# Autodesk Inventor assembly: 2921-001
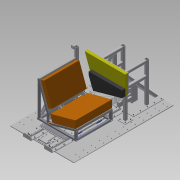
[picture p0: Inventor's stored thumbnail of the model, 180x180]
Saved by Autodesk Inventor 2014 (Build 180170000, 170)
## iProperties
Company: NHTSA/VRTC
Created: 2012-12
Part Number: 2921-001
Document SubType Name: Assembly
Designer: Mike Vanvoorhis
Project: CHILD SIDE IMPACT SLED
Description: CHILD SIDE IMPACT SLED ASS'Y.
Author: Dave Walker
Title: Child Side Impact Sled Ass'y.
Subject: Child Side Impact Sled
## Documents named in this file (22)
- B:\VRTC_DWG\BIO\Non-P572\Child Side-Frontal Impact Sled\Side Impact Sled\Sled_Buck_Assembly.iam
- B:\VRTC_DWG\BIO\Non-P572\Child Side-Frontal Impact Sled\Side Impact Sled\VRTC_Base_Plate.ipt
- B:\VRTC_DWG\BIO\Non-P572\Child Side-Frontal Impact Sled\Side Impact Sled\Impactor_Frame_Assembly_5.iam
- B:\VRTC_DWG\Inventor Support Files\Content Center\en-US\ANSI B18.3.1M(6)\ANSI B18.3.1M - M12x1.75 x 20(1).ipt
- B:\VRTC_DWG\BIO\Non-P572\Child Side-Frontal Impact Sled\Side Impact Sled\Rail_Assembly.iam
- B:\VRTC_DWG\Inventor Support Files\Content Center\en-US\ANSI B18.3(05)\ANSI B18.3 - 1_2-13 UNC - 1(31).ipt
- B:\VRTC_DWG\BIO\Non-P572\Child Side-Frontal Impact Sled\Side Impact Sled\Bench_Assembly.iam
- B:\VRTC_DWG\Inventor Support Files\Content Center\en-US\ANSI B18.3.1M(6)\ANSI B18.3.1M - M8x1.25 x 30(1).ipt
- B:\VRTC_DWG\BIO\Non-P572\Child Side-Frontal Impact Sled\Side Impact Sled\Anti_Rebound_Fixture_Assembly-01.iam
- B:\VRTC_DWG\BIO\Non-P572\Child Side Impact Sled-Nov 2012\Workspaces\Workspace\Inventor Models\Anti_Rebound_Fixture_Assembly.iam
- B:\VRTC_DWG\Inventor Support Files\Content Center\en-US\ANSI ASME B18.2.1(2)\ANSI_ASME B18.2.1 - 5_8-11 UNC - 1.5(2).ipt
- B:\VRTC_DWG\Inventor Support Files\Content Center\en-US\ANSI B18.21.1\ANSI B18.21.1 - 0.625.ipt
- B:\VRTC_DWG\Inventor Support Files\Content Center\en-US\ANSI B18.2.2(09)\ANSI B18.2.2 - 5_8 - 11(2).ipt
- B:\VRTC_DWG\BIO\Non-P572\Child Side-Frontal Impact Sled\Side Impact Sled\RightSide_Bumper.iam
- B:\VRTC_DWG\BIO\Non-P572\Child Side-Frontal Impact Sled\Side Impact Sled\LeftSide_Bumper.iam
- B:\VRTC_DWG\BIO\Non-P572\Child Side-Frontal Impact Sled\Side Impact Sled\Impactor Door Foam Assembly.iam
- B:\VRTC_DWG\BIO\Non-P572\Child Side-Frontal Impact Sled\Side Impact Sled\Honeycomb.ipt
- B:\VRTC_DWG\BIO\Non-P572\Child Side-Frontal Impact Sled\Side Impact Sled\Light Trap Mount Assembly.iam
- B:\VRTC_DWG\BIO\Non-P572\Child Side-Frontal Impact Sled\Side Impact Sled\Light Trap Sensor.ipt
- B:\VRTC_DWG\Inventor Support Files\Content Center\en-US\ANSI B18.3(05)\ANSI B18.3 - 3_8-24 UNF - 0.5(31).ipt
- B:\VRTC_DWG\Inventor Support Files\Content Center\en-US\ANSI ASME B18.2.1(2)\ANSI_ASME B18.2.1 - 5_8-11 UNC - 1.75(2).ipt
- B:\VRTC_DWG\Inventor Support Files\Content Center\en-US\ANSI B18.3(05)\ANSI B18.3 - 1_2-13 UNC - 1.25(31).ipt
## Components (117 placed, 20 different names)
1. VRTC_Base_Plate:1 — Insert:1, Angle:1, Insert:24, Insert:25, Insert:26, Insert:27, Insert:83, Insert:84, Insert:93, Insert:94, Insert:95, Insert:96, Insert:97, Insert:98, Insert:99, Insert:100, Flush:6, Insert:119, Insert:120, Insert:125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
2. Impactor_Frame_Assembly_5:1 [sub-assembly] — Insert:1, Angle:1, Insert:3, Insert:4, Insert:5, Insert:6, Insert:7, Insert:8, Insert:9, Insert:10, Insert:11, Insert:12, Insert:13, Insert:14, Insert:15, Insert:16, Insert:17, Insert:18, Insert:19, Insert:20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
3. Rail_Assembly:1 [sub-assembly] — Insert:24, Insert:25, Flush:1, Flush:2, Insert:49, Insert:50, Insert:51, Insert:52, Insert:53, Insert:54, Insert:55, Insert:56, Insert:57, Insert:58, Insert:59, Insert:60, Insert:61, Insert:62, Insert:63, Insert:64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
4. Rail_Assembly:2 [sub-assembly] — Insert:26, Insert:27, Flush:1, Flush:2, Insert:30, Insert:31, Insert:32, Insert:33, Insert:34, Insert:35, Insert:36, Insert:37, Insert:38, Insert:39, Insert:40, Insert:41, Insert:42, Insert:43, Insert:44, Insert:65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
5. Bench_Assembly:1 [sub-assembly] — Insert:64, Insert:65, Insert:66, Flush:6
6. Anti_Rebound_Fixture_Assembly-01:1 [sub-assembly] — Insert:83, Insert:84, Insert:85, Insert:86, Insert:87, Insert:88, Insert:89, Insert:90, Insert:91, Insert:92
7. RightSide_Bumper:1 [sub-assembly] — Insert:109, Insert:110
8. LeftSide_Bumper:1 [sub-assembly] — Insert:111, Insert:112
9. Impactor Door Foam Assembly:1 [sub-assembly] — Mate:1, Flush:3, Flush:4
10. Honeycomb:1 — Mate:2, Mate:3, Mate:4, Flush:5
11. Light Trap Mount Assembly:1 [sub-assembly] — Insert:119, Insert:120, Insert:121, Angle:2, Insert:122, Insert:123, Insert:124
12. Light Trap Sensor:1 — Insert:121, Angle:2
13. Hexagon Socket Head Cap Screw - Inch 3/8-24 UNF - 0.5:1 — Insert:122
14. Hex Bolt - Inch 5/8-11 UNC - 1.75:1 — Insert:124
15. Hex Bolt - Inch 5/8-11 UNC - 1.75:2 — Insert:123
16. Helical Spring Lock Washers 0.625:9 — Insert:126, Insert:127
17. Helical Spring Lock Washers 0.625:10 — Insert:125, Insert:128
18. Hex Nut - Inch 5/8 - 11:9 — Insert:127
19. Hex Nut - Inch 5/8 - 11:10 — Insert:128
20. Forged Socket Head Cap Screw - Metric M12x1.75 x 20:1
21. Forged Socket Head Cap Screw - Metric M12x1.75 x 20:2 — Insert:3
22. Forged Socket Head Cap Screw - Metric M12x1.75 x 20:3 — Insert:4
23. Forged Socket Head Cap Screw - Metric M12x1.75 x 20:4 — Insert:5
24. Forged Socket Head Cap Screw - Metric M12x1.75 x 20:5 — Insert:6
25. Forged Socket Head Cap Screw - Metric M12x1.75 x 20:6 — Insert:7
26. Forged Socket Head Cap Screw - Metric M12x1.75 x 20:7 — Insert:8
27. Forged Socket Head Cap Screw - Metric M12x1.75 x 20:8 — Insert:12
28. Forged Socket Head Cap Screw - Metric M12x1.75 x 20:9 — Insert:11
29. Forged Socket Head Cap Screw - Metric M12x1.75 x 20:10 — Insert:10
30. Forged Socket Head Cap Screw - Metric M12x1.75 x 20:11 — Insert:9
31. Forged Socket Head Cap Screw - Metric M12x1.75 x 20:12 — Insert:13
32. Forged Socket Head Cap Screw - Metric M12x1.75 x 20:13 — Insert:14
33. Forged Socket Head Cap Screw - Metric M12x1.75 x 20:14 — Insert:15
34. Forged Socket Head Cap Screw - Metric M12x1.75 x 20:15 — Insert:19
35. Forged Socket Head Cap Screw - Metric M12x1.75 x 20:16 — Insert:18
36. Forged Socket Head Cap Screw - Metric M12x1.75 x 20:17 — Insert:17
37. Forged Socket Head Cap Screw - Metric M12x1.75 x 20:18 — Insert:16
38. Forged Socket Head Cap Screw - Metric M12x1.75 x 20:19 — Insert:20
39. Forged Socket Head Cap Screw - Metric M12x1.75 x 20:20 — Insert:21
40. Forged Socket Head Cap Screw - Metric M12x1.75 x 20:21 — Insert:22
41. Forged Socket Head Cap Screw - Metric M12x1.75 x 20:22 — Insert:23
42. Hexagon Socket Head Cap Screw - Inch 1/2 - 13 UNC - 1:3 — Insert:30
43. Hexagon Socket Head Cap Screw - Inch 1/2 - 13 UNC - 1:4 — Insert:31
44. Hexagon Socket Head Cap Screw - Inch 1/2 - 13 UNC - 1:5 — Insert:32
45. Hexagon Socket Head Cap Screw - Inch 1/2 - 13 UNC - 1:6 — Insert:33
46. Hexagon Socket Head Cap Screw - Inch 1/2 - 13 UNC - 1:7 — Insert:34
47. Hexagon Socket Head Cap Screw - Inch 1/2 - 13 UNC - 1:8 — Insert:35
48. Hexagon Socket Head Cap Screw - Inch 1/2 - 13 UNC - 1:9 — Insert:36
49. Hexagon Socket Head Cap Screw - Inch 1/2 - 13 UNC - 1:10 — Insert:37
50. Hexagon Socket Head Cap Screw - Inch 1/2 - 13 UNC - 1:11 — Insert:38
51. Hexagon Socket Head Cap Screw - Inch 1/2 - 13 UNC - 1:12 — Insert:39
52. Hexagon Socket Head Cap Screw - Inch 1/2 - 13 UNC - 1:13 — Insert:40
53. Hexagon Socket Head Cap Screw - Inch 1/2 - 13 UNC - 1:14 — Insert:41
54. Hexagon Socket Head Cap Screw - Inch 1/2 - 13 UNC - 1:15 — Insert:42
55. Hexagon Socket Head Cap Screw - Inch 1/2 - 13 UNC - 1:16 — Insert:44
56. Hexagon Socket Head Cap Screw - Inch 1/2 - 13 UNC - 1:19 — Insert:49
57. Hexagon Socket Head Cap Screw - Inch 1/2 - 13 UNC - 1:20 — Insert:51
58. Hexagon Socket Head Cap Screw - Inch 1/2 - 13 UNC - 1:21 — Insert:52
59. Hexagon Socket Head Cap Screw - Inch 1/2 - 13 UNC - 1:22 — Insert:54
60. Hexagon Socket Head Cap Screw - Inch 1/2 - 13 UNC - 1:23 — Insert:57
61. Hexagon Socket Head Cap Screw - Inch 1/2 - 13 UNC - 1:24 — Insert:58
62. Hexagon Socket Head Cap Screw - Inch 1/2 - 13 UNC - 1:25 — Insert:60
63. Hexagon Socket Head Cap Screw - Inch 1/2 - 13 UNC - 1:26 — Insert:63
64. Hexagon Socket Head Cap Screw - Inch 1/2 - 13 UNC - 1:27 — Insert:62
65. Hexagon Socket Head Cap Screw - Inch 1/2 - 13 UNC - 1:28 — Insert:61
66. Hexagon Socket Head Cap Screw - Inch 1/2 - 13 UNC - 1:29 — Insert:59
67. Hexagon Socket Head Cap Screw - Inch 1/2 - 13 UNC - 1:30 — Insert:56
68. Hexagon Socket Head Cap Screw - Inch 1/2 - 13 UNC - 1:31 — Insert:55
69. Hexagon Socket Head Cap Screw - Inch 1/2 - 13 UNC - 1:32 — Insert:53
70. Hexagon Socket Head Cap Screw - Inch 1/2 - 13 UNC - 1:33 — Insert:50
71. Hexagon Socket Head Cap Screw - Inch 1/2 - 13 UNC - 1:35 — Insert:43
72. Forged Socket Head Cap Screw - Metric M8x1.25 x 30:1 — Insert:67
73. Forged Socket Head Cap Screw - Metric M8x1.25 x 30:2 — Insert:68
74. Forged Socket Head Cap Screw - Metric M8x1.25 x 30:3 — Insert:69
75. Forged Socket Head Cap Screw - Metric M8x1.25 x 30:4 — Insert:70
76. Forged Socket Head Cap Screw - Metric M8x1.25 x 30:5 — Insert:72
77. Forged Socket Head Cap Screw - Metric M8x1.25 x 30:6 — Insert:71
78. Forged Socket Head Cap Screw - Metric M8x1.25 x 30:7 — Insert:73
79. Forged Socket Head Cap Screw - Metric M8x1.25 x 30:8 — Insert:74
80. Forged Socket Head Cap Screw - Metric M8x1.25 x 30:9 — Insert:75
81. Forged Socket Head Cap Screw - Metric M8x1.25 x 30:10 — Insert:76
82. Forged Socket Head Cap Screw - Metric M8x1.25 x 30:11 — Insert:78
83. Forged Socket Head Cap Screw - Metric M8x1.25 x 30:12 — Insert:77
84. Forged Socket Head Cap Screw - Metric M8x1.25 x 30:13 — Insert:79
85. Forged Socket Head Cap Screw - Metric M8x1.25 x 30:14 — Insert:80
86. Forged Socket Head Cap Screw - Metric M8x1.25 x 30:15 — Insert:81
87. Forged Socket Head Cap Screw - Metric M8x1.25 x 30:16 — Insert:82
88. Hex Bolt - Inch 5/8-11 UNC - 1.5:1 — Insert:85
89. Hex Bolt - Inch 5/8-11 UNC - 1.5:2 — Insert:86
90. Hex Bolt - Inch 5/8-11 UNC - 1.5:3 — Insert:87
91. Hex Bolt - Inch 5/8-11 UNC - 1.5:4 — Insert:88
92. Hex Bolt - Inch 5/8-11 UNC - 1.5:5 — Insert:89
93. Hex Bolt - Inch 5/8-11 UNC - 1.5:6 — Insert:90
94. Hex Bolt - Inch 5/8-11 UNC - 1.5:7 — Insert:91
95. Hex Bolt - Inch 5/8-11 UNC - 1.5:8 — Insert:92
96. Helical Spring Lock Washers 0.625:1 — Insert:97, Insert:105
97. Helical Spring Lock Washers 0.625:2 — Insert:99, Insert:107
98. Helical Spring Lock Washers 0.625:3 — Insert:98, Insert:106
99. Helical Spring Lock Washers 0.625:4 — Insert:100, Insert:108
100. Helical Spring Lock Washers 0.625:5 — Insert:96, Insert:104
101. Helical Spring Lock Washers 0.625:6 — Insert:93, Insert:101
102. Helical Spring Lock Washers 0.625:7 — Insert:95, Insert:103
103. Helical Spring Lock Washers 0.625:8 — Insert:94, Insert:102
104. Hex Nut - Inch 5/8 - 11:1 — Insert:101
105. Hex Nut - Inch 5/8 - 11:2 — Insert:102
106. Hex Nut - Inch 5/8 - 11:3 — Insert:103
107. Hex Nut - Inch 5/8 - 11:4 — Insert:104
108. Hex Nut - Inch 5/8 - 11:5 — Insert:105
109. Hex Nut - Inch 5/8 - 11:6 — Insert:106
110. Hex Nut - Inch 5/8 - 11:7 — Insert:108
111. Hex Nut - Inch 5/8 - 11:8 — Insert:107
112. Hexagon Socket Head Cap Screw - Inch 1/2 - 13 UNC - 1 1/4:1
113. Hexagon Socket Head Cap Screw - Inch 1/2 - 13 UNC - 1 1/4:2
114. Hexagon Socket Head Cap Screw - Inch 1/2 - 13 UNC - 1 1/4:3
115. Hexagon Socket Head Cap Screw - Inch 1/2 - 13 UNC - 1 1/4:4
116. Hexagon Socket Head Cap Screw - Inch 1/2 - 13 UNC - 1 1/4:5
117. Hexagon Socket Head Cap Screw - Inch 1/2 - 13 UNC - 1 1/4:6
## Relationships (127: Insert 115, Flush 6, Mate 4, Angle 2)
- Insert:1: VRTC_Base_Plate:1 ↔ Impactor_Frame_Assembly_5:1
- Angle:1: VRTC_Base_Plate:1 ↔ Impactor_Frame_Assembly_5:1
- Insert:3: Impactor_Frame_Assembly_5:1 ↔ Forged Socket Head Cap Screw - Metric M12x1.75 x 20:2
- Insert:4: Impactor_Frame_Assembly_5:1 ↔ Forged Socket Head Cap Screw - Metric M12x1.75 x 20:3
- Insert:5: Impactor_Frame_Assembly_5:1 ↔ Forged Socket Head Cap Screw - Metric M12x1.75 x 20:4
- Insert:6: Impactor_Frame_Assembly_5:1 ↔ Forged Socket Head Cap Screw - Metric M12x1.75 x 20:5
- Insert:7: Impactor_Frame_Assembly_5:1 ↔ Forged Socket Head Cap Screw - Metric M12x1.75 x 20:6
- Insert:8: Impactor_Frame_Assembly_5:1 ↔ Forged Socket Head Cap Screw - Metric M12x1.75 x 20:7
- Insert:9: Impactor_Frame_Assembly_5:1 ↔ Forged Socket Head Cap Screw - Metric M12x1.75 x 20:11
- Insert:10: Impactor_Frame_Assembly_5:1 ↔ Forged Socket Head Cap Screw - Metric M12x1.75 x 20:10
- Insert:11: Impactor_Frame_Assembly_5:1 ↔ Forged Socket Head Cap Screw - Metric M12x1.75 x 20:9
- Insert:12: Impactor_Frame_Assembly_5:1 ↔ Forged Socket Head Cap Screw - Metric M12x1.75 x 20:8
- Insert:13: Impactor_Frame_Assembly_5:1 ↔ Forged Socket Head Cap Screw - Metric M12x1.75 x 20:12
- Insert:14: Impactor_Frame_Assembly_5:1 ↔ Forged Socket Head Cap Screw - Metric M12x1.75 x 20:13
- Insert:15: Impactor_Frame_Assembly_5:1 ↔ Forged Socket Head Cap Screw - Metric M12x1.75 x 20:14
- Insert:16: Impactor_Frame_Assembly_5:1 ↔ Forged Socket Head Cap Screw - Metric M12x1.75 x 20:18
- Insert:17: Impactor_Frame_Assembly_5:1 ↔ Forged Socket Head Cap Screw - Metric M12x1.75 x 20:17
- Insert:18: Impactor_Frame_Assembly_5:1 ↔ Forged Socket Head Cap Screw - Metric M12x1.75 x 20:16
- Insert:19: Impactor_Frame_Assembly_5:1 ↔ Forged Socket Head Cap Screw - Metric M12x1.75 x 20:15
- Insert:20: Impactor_Frame_Assembly_5:1 ↔ Forged Socket Head Cap Screw - Metric M12x1.75 x 20:19
- Insert:21: Impactor_Frame_Assembly_5:1 ↔ Forged Socket Head Cap Screw - Metric M12x1.75 x 20:20
- Insert:22: Impactor_Frame_Assembly_5:1 ↔ Forged Socket Head Cap Screw - Metric M12x1.75 x 20:21
- Insert:23: Impactor_Frame_Assembly_5:1 ↔ Forged Socket Head Cap Screw - Metric M12x1.75 x 20:22
- Insert:24: VRTC_Base_Plate:1 ↔ Rail_Assembly:1
- Insert:25: VRTC_Base_Plate:1 ↔ Rail_Assembly:1
- Insert:26: VRTC_Base_Plate:1 ↔ Rail_Assembly:2
- Insert:27: VRTC_Base_Plate:1 ↔ Rail_Assembly:2
- Flush:1: Rail_Assembly:1 ↔ Rail_Assembly:2
- Flush:2: Rail_Assembly:1 ↔ Rail_Assembly:2
- Insert:30: Rail_Assembly:2 ↔ Hexagon Socket Head Cap Screw - Inch 1/2 - 13 UNC - 1:3
- Insert:31: Rail_Assembly:2 ↔ Hexagon Socket Head Cap Screw - Inch 1/2 - 13 UNC - 1:4
- Insert:32: Rail_Assembly:2 ↔ Hexagon Socket Head Cap Screw - Inch 1/2 - 13 UNC - 1:5
- Insert:33: Rail_Assembly:2 ↔ Hexagon Socket Head Cap Screw - Inch 1/2 - 13 UNC - 1:6
- Insert:34: Rail_Assembly:2 ↔ Hexagon Socket Head Cap Screw - Inch 1/2 - 13 UNC - 1:7
- Insert:35: Rail_Assembly:2 ↔ Hexagon Socket Head Cap Screw - Inch 1/2 - 13 UNC - 1:8
- Insert:36: Rail_Assembly:2 ↔ Hexagon Socket Head Cap Screw - Inch 1/2 - 13 UNC - 1:9
- Insert:37: Rail_Assembly:2 ↔ Hexagon Socket Head Cap Screw - Inch 1/2 - 13 UNC - 1:10
- Insert:38: Rail_Assembly:2 ↔ Hexagon Socket Head Cap Screw - Inch 1/2 - 13 UNC - 1:11
- Insert:39: Rail_Assembly:2 ↔ Hexagon Socket Head Cap Screw - Inch 1/2 - 13 UNC - 1:12
- Insert:40: Rail_Assembly:2 ↔ Hexagon Socket Head Cap Screw - Inch 1/2 - 13 UNC - 1:13
- Insert:41: Rail_Assembly:2 ↔ Hexagon Socket Head Cap Screw - Inch 1/2 - 13 UNC - 1:14
- Insert:42: Rail_Assembly:2 ↔ Hexagon Socket Head Cap Screw - Inch 1/2 - 13 UNC - 1:15
- Insert:43: Rail_Assembly:2 ↔ Hexagon Socket Head Cap Screw - Inch 1/2 - 13 UNC - 1:35
- Insert:44: Rail_Assembly:2 ↔ Hexagon Socket Head Cap Screw - Inch 1/2 - 13 UNC - 1:16
- Insert:49: Rail_Assembly:1 ↔ Hexagon Socket Head Cap Screw - Inch 1/2 - 13 UNC - 1:19
- Insert:50: Rail_Assembly:1 ↔ Hexagon Socket Head Cap Screw - Inch 1/2 - 13 UNC - 1:33
- Insert:51: Rail_Assembly:1 ↔ Hexagon Socket Head Cap Screw - Inch 1/2 - 13 UNC - 1:20
- Insert:52: Rail_Assembly:1 ↔ Hexagon Socket Head Cap Screw - Inch 1/2 - 13 UNC - 1:21
- Insert:53: Rail_Assembly:1 ↔ Hexagon Socket Head Cap Screw - Inch 1/2 - 13 UNC - 1:32
- Insert:54: Rail_Assembly:1 ↔ Hexagon Socket Head Cap Screw - Inch 1/2 - 13 UNC - 1:22
- Insert:55: Rail_Assembly:1 ↔ Hexagon Socket Head Cap Screw - Inch 1/2 - 13 UNC - 1:31
- Insert:56: Rail_Assembly:1 ↔ Hexagon Socket Head Cap Screw - Inch 1/2 - 13 UNC - 1:30
- Insert:57: Rail_Assembly:1 ↔ Hexagon Socket Head Cap Screw - Inch 1/2 - 13 UNC - 1:23
- Insert:58: Rail_Assembly:1 ↔ Hexagon Socket Head Cap Screw - Inch 1/2 - 13 UNC - 1:24
- Insert:59: Rail_Assembly:1 ↔ Hexagon Socket Head Cap Screw - Inch 1/2 - 13 UNC - 1:29
- Insert:60: Rail_Assembly:1 ↔ Hexagon Socket Head Cap Screw - Inch 1/2 - 13 UNC - 1:25
- Insert:61: Rail_Assembly:1 ↔ Hexagon Socket Head Cap Screw - Inch 1/2 - 13 UNC - 1:28
- Insert:62: Rail_Assembly:1 ↔ Hexagon Socket Head Cap Screw - Inch 1/2 - 13 UNC - 1:27
- Insert:63: Rail_Assembly:1 ↔ Hexagon Socket Head Cap Screw - Inch 1/2 - 13 UNC - 1:26
- Insert:64: Rail_Assembly:1 ↔ Bench_Assembly:1
- Insert:65: Rail_Assembly:2 ↔ Bench_Assembly:1
- Insert:66: Rail_Assembly:2 ↔ Bench_Assembly:1
- Insert:67: Rail_Assembly:2 ↔ Forged Socket Head Cap Screw - Metric M8x1.25 x 30:1
- Insert:68: Rail_Assembly:2 ↔ Forged Socket Head Cap Screw - Metric M8x1.25 x 30:2
- Insert:69: Rail_Assembly:1 ↔ Forged Socket Head Cap Screw - Metric M8x1.25 x 30:3
- Insert:70: Rail_Assembly:1 ↔ Forged Socket Head Cap Screw - Metric M8x1.25 x 30:4
- Insert:71: Rail_Assembly:1 ↔ Forged Socket Head Cap Screw - Metric M8x1.25 x 30:6
- Insert:72: Rail_Assembly:1 ↔ Forged Socket Head Cap Screw - Metric M8x1.25 x 30:5
- Insert:73: Rail_Assembly:2 ↔ Forged Socket Head Cap Screw - Metric M8x1.25 x 30:7
- Insert:74: Rail_Assembly:2 ↔ Forged Socket Head Cap Screw - Metric M8x1.25 x 30:8
- Insert:75: Rail_Assembly:1 ↔ Forged Socket Head Cap Screw - Metric M8x1.25 x 30:9
- Insert:76: Rail_Assembly:1 ↔ Forged Socket Head Cap Screw - Metric M8x1.25 x 30:10
- Insert:77: Rail_Assembly:2 ↔ Forged Socket Head Cap Screw - Metric M8x1.25 x 30:12
- Insert:78: Rail_Assembly:2 ↔ Forged Socket Head Cap Screw - Metric M8x1.25 x 30:11
- Insert:79: Rail_Assembly:2 ↔ Forged Socket Head Cap Screw - Metric M8x1.25 x 30:13
- Insert:80: Rail_Assembly:2 ↔ Forged Socket Head Cap Screw - Metric M8x1.25 x 30:14
- Insert:81: Rail_Assembly:1 ↔ Forged Socket Head Cap Screw - Metric M8x1.25 x 30:15
- Insert:82: Rail_Assembly:1 ↔ Forged Socket Head Cap Screw - Metric M8x1.25 x 30:16
- Insert:83: VRTC_Base_Plate:1 ↔ Anti_Rebound_Fixture_Assembly-01:1
- Insert:84: VRTC_Base_Plate:1 ↔ Anti_Rebound_Fixture_Assembly-01:1
- Insert:85: Anti_Rebound_Fixture_Assembly-01:1 ↔ Hex Bolt - Inch 5/8-11 UNC - 1.5:1
- Insert:86: Anti_Rebound_Fixture_Assembly-01:1 ↔ Hex Bolt - Inch 5/8-11 UNC - 1.5:2
- Insert:87: Anti_Rebound_Fixture_Assembly-01:1 ↔ Hex Bolt - Inch 5/8-11 UNC - 1.5:3
- Insert:88: Anti_Rebound_Fixture_Assembly-01:1 ↔ Hex Bolt - Inch 5/8-11 UNC - 1.5:4
- Insert:89: Anti_Rebound_Fixture_Assembly-01:1 ↔ Hex Bolt - Inch 5/8-11 UNC - 1.5:5
- Insert:90: Anti_Rebound_Fixture_Assembly-01:1 ↔ Hex Bolt - Inch 5/8-11 UNC - 1.5:6
- Insert:91: Anti_Rebound_Fixture_Assembly-01:1 ↔ Hex Bolt - Inch 5/8-11 UNC - 1.5:7
- Insert:92: Anti_Rebound_Fixture_Assembly-01:1 ↔ Hex Bolt - Inch 5/8-11 UNC - 1.5:8
- Insert:93: VRTC_Base_Plate:1 ↔ Helical Spring Lock Washers 0.625:6
- Insert:94: VRTC_Base_Plate:1 ↔ Helical Spring Lock Washers 0.625:8
- Insert:95: VRTC_Base_Plate:1 ↔ Helical Spring Lock Washers 0.625:7
- Insert:96: VRTC_Base_Plate:1 ↔ Helical Spring Lock Washers 0.625:5
- Insert:97: VRTC_Base_Plate:1 ↔ Helical Spring Lock Washers 0.625:1
- Insert:98: VRTC_Base_Plate:1 ↔ Helical Spring Lock Washers 0.625:3
- Insert:99: VRTC_Base_Plate:1 ↔ Helical Spring Lock Washers 0.625:2
- Insert:100: VRTC_Base_Plate:1 ↔ Helical Spring Lock Washers 0.625:4
- Insert:101: Helical Spring Lock Washers 0.625:6 ↔ Hex Nut - Inch 5/8 - 11:1
- Insert:102: Helical Spring Lock Washers 0.625:8 ↔ Hex Nut - Inch 5/8 - 11:2
- Insert:103: Helical Spring Lock Washers 0.625:7 ↔ Hex Nut - Inch 5/8 - 11:3
- Insert:104: Helical Spring Lock Washers 0.625:5 ↔ Hex Nut - Inch 5/8 - 11:4
- Insert:105: Helical Spring Lock Washers 0.625:1 ↔ Hex Nut - Inch 5/8 - 11:5
- Insert:106: Helical Spring Lock Washers 0.625:3 ↔ Hex Nut - Inch 5/8 - 11:6
- Insert:107: Helical Spring Lock Washers 0.625:2 ↔ Hex Nut - Inch 5/8 - 11:8
- Insert:108: Helical Spring Lock Washers 0.625:4 ↔ Hex Nut - Inch 5/8 - 11:7
- Insert:109: Rail_Assembly:2 ↔ RightSide_Bumper:1
- Insert:110: Rail_Assembly:2 ↔ RightSide_Bumper:1
- Insert:111: Rail_Assembly:1 ↔ LeftSide_Bumper:1
- Insert:112: Rail_Assembly:1 ↔ LeftSide_Bumper:1
- Mate:1: Impactor_Frame_Assembly_5:1 ↔ Impactor Door Foam Assembly:1
- Flush:3: Impactor_Frame_Assembly_5:1 ↔ Impactor Door Foam Assembly:1
- Flush:4: Impactor_Frame_Assembly_5:1 ↔ Impactor Door Foam Assembly:1
- Mate:2: Impactor_Frame_Assembly_5:1 ↔ Honeycomb:1
- Mate:3: Impactor_Frame_Assembly_5:1 ↔ Honeycomb:1
- Mate:4: Impactor_Frame_Assembly_5:1 ↔ Honeycomb:1
- Flush:5: Impactor_Frame_Assembly_5:1 ↔ Honeycomb:1
- Flush:6: VRTC_Base_Plate:1 ↔ Bench_Assembly:1
- Insert:119: VRTC_Base_Plate:1 ↔ Light Trap Mount Assembly:1
- Insert:120: VRTC_Base_Plate:1 ↔ Light Trap Mount Assembly:1
- Insert:121: Light Trap Mount Assembly:1 ↔ Light Trap Sensor:1
- Angle:2: Light Trap Mount Assembly:1 ↔ Light Trap Sensor:1
- Insert:122: Light Trap Mount Assembly:1 ↔ Hexagon Socket Head Cap Screw - Inch 3/8-24 UNF - 0.5:1
- Insert:123: Light Trap Mount Assembly:1 ↔ Hex Bolt - Inch 5/8-11 UNC - 1.75:2
- Insert:124: Light Trap Mount Assembly:1 ↔ Hex Bolt - Inch 5/8-11 UNC - 1.75:1
- Insert:125: VRTC_Base_Plate:1 ↔ Helical Spring Lock Washers 0.625:10
- Insert:126: VRTC_Base_Plate:1 ↔ Helical Spring Lock Washers 0.625:9
- Insert:127: Helical Spring Lock Washers 0.625:9 ↔ Hex Nut - Inch 5/8 - 11:9
- Insert:128: Helical Spring Lock Washers 0.625:10 ↔ Hex Nut - Inch 5/8 - 11:10
